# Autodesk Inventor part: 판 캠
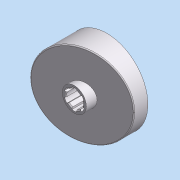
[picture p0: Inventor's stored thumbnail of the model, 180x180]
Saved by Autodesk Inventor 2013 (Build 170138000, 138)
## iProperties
Company: 한국ATC센터
Created: 2014-07
Part Number: 판 캠
Document SubType Name: 모델링
Designer: KYOUNG IL JANG
Material: 강철
Density: 7.85 g/cm^3
Mass: 681.586 g
Surface Area: 331.301 cm^2
Volume: 86.8262 cm^3
변환 표준: STEP AP214IS
파일 이름: C:\Users\SeoGD\Desktop\?쒗뿕\??stp
전처리기: Build: 253, Release: 2010 SP1 - Date: Wed 07/29/2009
전송 단위: 밀리미터
불확실성: 0.01
Author: KYOUNG IL JANG
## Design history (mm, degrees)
node "작업 평면4"
sketch "스케치1"
  geometry: C1 r 44.5 at (0, 0); 1 further point
  constraints: 1 centre point, 1 coincident
  dimensions: "d25" = 89 diameter of C1
extrude "돌출1" new body sketch "스케치1" distance "d1" = 40; taper "d2" = 0 deg
sketch "스케치2"
  geometry: L1 (-44.5, 15)-(44.5, 38.847); L2 (-44.5, 0)-(-44.5, 40) reference; L3 (-44.5, 40)-(44.5, 40) reference; L4 (44.5, 0)-(44.5, 40) reference; 1 further point
  constraints: 2 end point, 2 point on line
  dimensions: "d26" = 15 distance of L2.start L1.start; "d27" = 75 deg angle of L1 L2
extrude "돌출2" cut sketch "스케치2" stored distance "d5" = 40; taper "d6" = 0 deg
node "작업 평면1"
sketch "스케치3"
  geometry: C1 r 13 at (0, 0); 1 further point
  constraints: 1 centre point, 1 coincident
  dimensions: "d9" = 26 diameter of C1
extrude "돌출3" join sketch "스케치3" distance "d10" = 38; taper "d11" = 0 deg
hole "구멍1" diameter "d14" = 18; stored, may be unused: countersink angle "d18" = 90 deg, drill point angle "d20" = 118 deg; dims "d12" = 10, "d13" = 10, "d15" = 6, "d16" = 4, "d17" = 2, "d19" = 8
feature "쉘2" dims "d29" = 5
sketch "스케치6"
  geometry: C1 r 17.5 at (0, 0); C2 r 14 at (0, 0) reference; 1 further point
  constraints: 1 centre point, 1 coincident
  dimensions: "d28" = 35 diameter of C1
extrude "돌출4" join sketch "스케치6" stored distance "d30" = 38; taper "d31" = 0 deg
fillet "모깎기1" dims "d32" = 3
chamfer "모따기1" distance "d21" = 1; stored, may be unused: second distance "d22" = 2, angle "d23" = 45 deg
sketch "스케치7"
  geometry: L1 (-12.374, 12.374)-(-27.931, 27.931); A1 r 39.5 centre (0, 0) between (-27.931, 27.931) and (0, 39.5) reference; 2 further points
  constraints: 2 end point, 2 point on circle, 1 point on line, 1 vertical alignment, 2 other
  dimensions: "d33" = 45 deg dimension on point (0, 0) L1.start A1.end
feature "리브1" sketch "스케치7" dims "d34" = 5, "d35" = 1, "d36" = 0
fillet "모깎기2" dims "d37" = 3
sketch "스케치8"
  geometry: L1 (2.5, 10.712)-(2.5, 8.646); L2 (-2.5, 10.712)-(-2.5, 8.646); A1 r 11 centre (0, 0) between (2.5, 10.712) and (-2.5, 10.712); A2 r 9 centre (0, 0) between (2.5, 8.646) and (-2.5, 8.646) reference; 1 further point
  constraints: 4 end point, 4 point on circle, 2 parallel, 1 centre point, 1 coincident, 1 vertical
  dimensions: "d41" = 22 diameter of A1; "d42" = 5 distance between parallel lines of L1 L2
extrude "돌출5" cut sketch "스케치8" stored distance "d43" = 38; taper "d44" = 0 deg
fillet "모깎기3" dims "d48" = 1
node "솔리드1"
node "솔리드 본체"
node "곡면 본체"
pattern_circular "원형 패턴1" dims angle "d39" = 360 deg
pattern_circular "원형 패턴2" dims angle "d46" = 360 deg
node "솔리드2"
